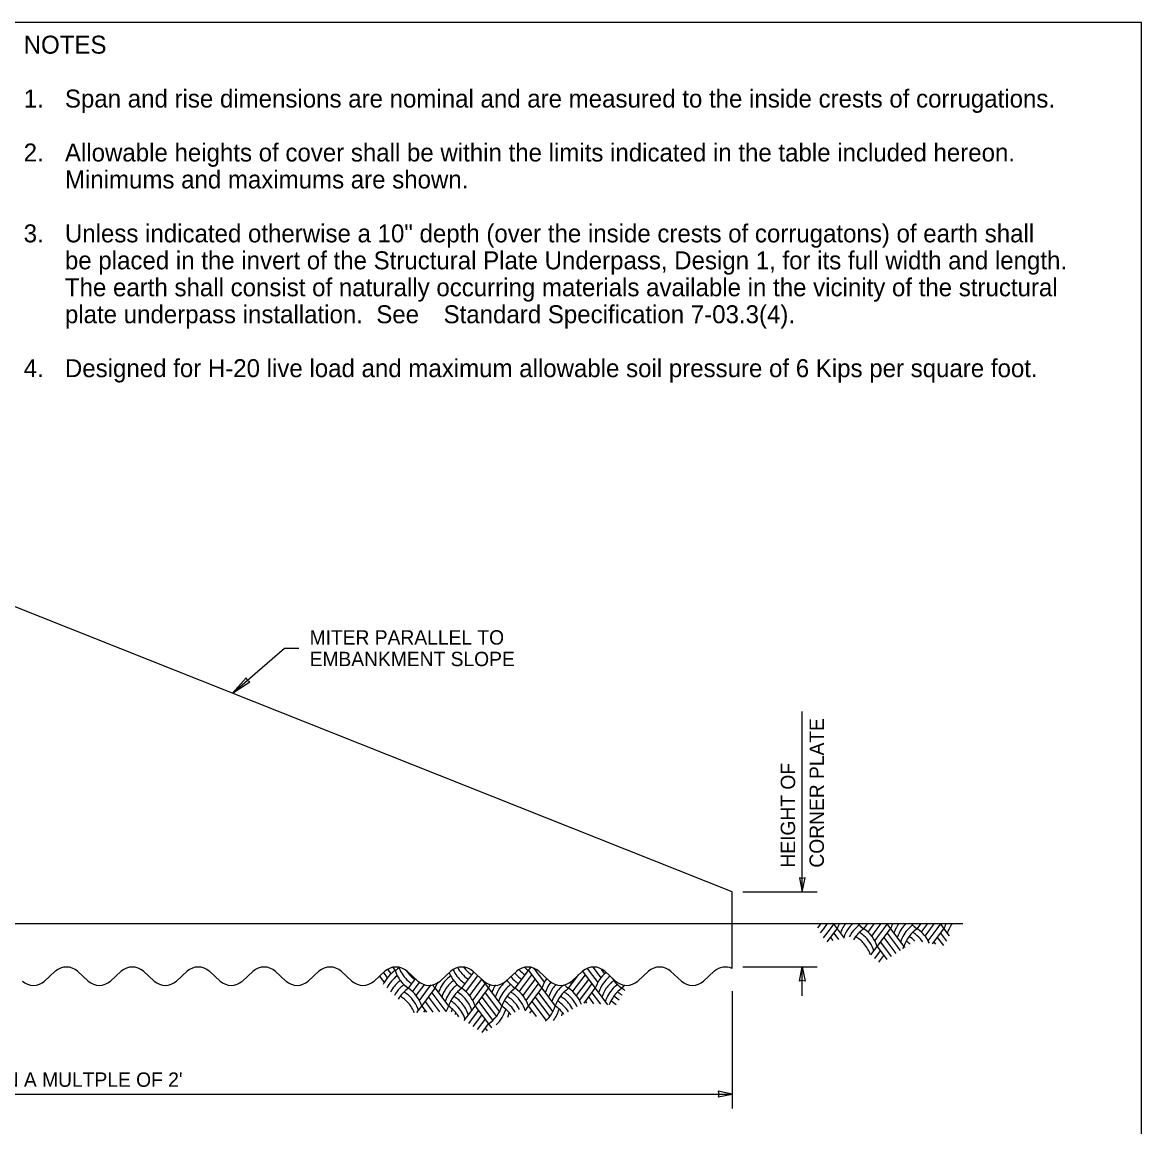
# Model space of a CAD drawing. Extents: x 99862 to 103151, y 100000 to 102076.
# Drawn here: x 101906 to 103151, y 100847 to 102076 of the extents above; entities that cross this region are included whole.
import ezdxf

# ---------------------------------------------------------------- set-up
doc = ezdxf.new("R2010")
doc.units = 0
for name, color, linetype in [('Level 1', 7, 'Continuous'), ('Level 11', 7, 'Continuous'), ('Level 15', 7, 'Continuous'), ('Level 20', 7, 'Continuous'), ('Level 40', 7, 'Continuous'), ('Level 6', 7, 'Continuous'), ('Level 60', 7, 'Continuous'), ('Level 62', 7, 'Continuous')]:
    doc.layers.add(name, color=color, linetype=linetype)

msp = doc.modelspace()

# ---------------------------------------------------------------- linework, layer by layer
at = {"layer": 'Level 1'}
msp.add_lwpolyline([(99862, 99999.5), (103151, 99999.5), (103151, 102075.5), (99862, 102075.5)], close=True, dxfattribs=at)
at = {"layer": 'Level 11'}
for p, q in [((102303, 101014), (102308.3, 101007)), ((102307.4, 101018.1), (102311.7, 101012.3)), ((102312.3, 101021.4), (102315.8, 101016.7)), ((102318, 101023.7), (102320.5, 101020.4)), ((102394.7, 101000.6), (102408.2, 101018.6)), ((102402.1, 101000.6), (102412.6, 101014.5)), ((102454.1, 101000.6), (102469, 101020.4)), ((102461.5, 101000.6), (102472.7, 101015.5)), ((102469, 101020.4), (102471.5, 101023.9)), ((102469, 101020.4), (102483.8, 101000.6)), ((102474.8, 101022.5), (102486.5, 101007)), ((102513.5, 101000.6), (102524.9, 101015.8)), ((102520.9, 101000.6), (102532.1, 101015.5)), ((102529, 101019.6), (102543.2, 101000.6)), ((102534.2, 101022.5), (102545.9, 101007)), ((102540.7, 101023.8), (102549.3, 101012.3)), ((102549.7, 101021.7), (102553.4, 101016.7)), ((102335.3, 101000.6), (102343.1, 101011)), ((102342.7, 101000.6), (102347.8, 101007.4)), ((102350.2, 101000.6), (102353.1, 101004.6)), ((102357.6, 101000.6), (102360.4, 101004.4)), ((102362.2, 101004.3), (102365, 101000.6)), ((102367.5, 101007.1), (102367.7, 101007)), ((102409.6, 101000.6), (102417, 101010.5)), ((102417, 101010.5), (102424.4, 101000.6)), ((102417, 101000.6), (102420.7, 101005.6)), ((102469, 101000.6), (102476.4, 101010.5)), ((102476.4, 101000.6), (102480.1, 101005.6)), ((102528.4, 101000.6), (102535.8, 101010.5)), ((102535.8, 101000.6), (102539.5, 101005.6)), ((102572.9, 101000.6), (102575.9, 101004.6)), ((102340, 100996.9), (102342.7, 101000.6)), ((102344, 100992.5), (102350.2, 101000.6)), ((102347.5, 100987.2), (102357.6, 101000.6)), ((102350.2, 100980.8), (102365, 101000.6)), ((102357.6, 100990.7), (102369.8, 100974.5)), ((102361.3, 100995.7), (102377, 100974.7)), ((102365, 101000.6), (102379.9, 100980.8)), ((102399.4, 100996.9), (102402.1, 101000.6)), ((102403.4, 100992.5), (102409.6, 101000.6)), ((102406.9, 100987.2), (102417, 101000.6)), ((102409.6, 100980.8), (102424.4, 101000.6)), ((102417, 100990.7), (102433.1, 100969.2)), ((102420.7, 100995.7), (102436.6, 100974.5)), ((102424.4, 101000.6), (102439.3, 100980.8)), ((102458.8, 100996.9), (102461.5, 101000.6)), ((102462.8, 100992.5), (102469, 101000.6)), ((102466.3, 100987.2), (102476.4, 101000.6)), ((102469, 100980.8), (102483.8, 101000.6)), ((102476.4, 100990.7), (102492.5, 100969.2)), ((102480.1, 100995.7), (102496, 100974.5)), ((102483.8, 101000.6), (102498.7, 100980.8)), ((102518.2, 100996.9), (102520.9, 101000.6)), ((102522.2, 100992.5), (102528.4, 101000.6)), ((102525.7, 100987.2), (102535.8, 101000.6)), ((102530.9, 100984.2), (102543.2, 101000.6)), ((102535.8, 100990.7), (102541.2, 100983.5)), ((102539.5, 100995.7), (102549, 100983)), ((102543.2, 101000.6), (102556.9, 100982.4)), ((102344.7, 100973.6), (102350.2, 100980.8)), ((102350.2, 100980.8), (102355.3, 100974)), ((102353.9, 100985.8), (102362.5, 100974.2)), ((102397.4, 100964.7), (102409.6, 100980.8)), ((102409.6, 100980.8), (102424.4, 100961)), ((102413.3, 100985.8), (102429.1, 100964.7)), ((102465, 100975.5), (102469, 100980.8)), ((102469, 100980.8), (102477.5, 100969.4)), ((102472.7, 100985.8), (102488.5, 100964.7)), ((102532.1, 100985.8), (102533.4, 100984)), ((102352.3, 100973.9), (102353.9, 100975.9)), ((102402.4, 100961.4), (102413.3, 100975.9)), ((102407.3, 100958.1), (102417, 100970.9)), ((102412.3, 100954.8), (102420.7, 100966)), ((102470.4, 100972.9), (102472.7, 100975.9)), ((102475.8, 100970.2), (102476.4, 100970.9)), ((102417.2, 100951.5), (102424.4, 100961)), ((102420.7, 100956.1), (102422.9, 100953.2)), ((102424.4, 100961), (102427.8, 100956.5))]:
    msp.add_line(p, q, dxfattribs=at)
for centre, start, end in [((102341.4, 100989.2), 123.9036, 155.3622), ((102345.1, 100984.3), 126.3063, 153.8683), ((102299.5, 101051.6), 303.9036, 312.3733), ((102356.3, 101031.8), 197.6434, 236.0964), ((102360, 101036.8), 200.2432, 228.9599), ((102363.7, 101041.7), 215.4772, 220.9416), ((102363.7, 101041.7), 220.9415, 236.0964), ((102404.5, 100984.3), 126.3063, 154.2266), ((102415.7, 101031.8), 201.4874, 236.0964), ((102419.4, 101036.8), 204.5498, 228.9599), ((102423.1, 101041.7), 208.7333, 220.9416), ((102423.1, 101041.7), 220.9415, 236.0964), ((102426.8, 101046.7), 217.4338, 236.0964), ((102482.5, 101041.7), 219.7756, 220.9416), ((102482.5, 101041.7), 220.9415, 236.0964), ((102486.2, 101046.7), 222.6882, 236.0964), ((102489.9, 101051.6), 228.0122, 236.0964), ((102545.6, 101046.7), 235.9753, 236.0964), ((102579, 100989.2), 129.4402, 162.3566), ((102582.7, 100984.3), 127.6651, 154.2266), ((102348.8, 100979.3), 127.1006, 145.4911), ((102352.6, 100974.4), 126.331, 135.7128), ((102360, 101036.8), 228.9599, 236.0964), ((102400.8, 100989.2), 151.2509, 162.3566), ((102408.2, 100979.3), 127.1006, 145.4911), ((102412, 100974.4), 126.331, 135.7128), ((102419.4, 101036.8), 228.9599, 236.0964), ((102460.2, 100989.2), 155.6268, 162.3566), ((102463.9, 100984.3), 147.6019, 154.2266), ((102467.6, 100979.3), 127.1006, 145.4911), ((102471.4, 100974.4), 126.331, 135.7128), ((102475.1, 101031.8), 216.2594, 236.0964), ((102478.8, 101036.8), 218.0196, 228.9599), ((102478.8, 101036.8), 228.9599, 236.0964), ((102519.6, 100989.2), 143.8002, 162.3566), ((102523.3, 100984.3), 141.3871, 154.2266), ((102527, 100979.3), 137.4919, 145.4911), ((102530.7, 100974.4), 127.1068, 135.7128), ((102534.5, 101031.8), 226.9894, 236.0964), ((102538.2, 101036.8), 231.3576, 236.0964), ((102541.9, 101041.7), 234.179, 236.0964), ((102586.4, 100979.3), 127.1006, 145.4911), ((102593.9, 101031.8), 211.6153, 236.0964), ((102590.1, 100974.4), 126.331, 135.7128), ((102348.8, 100979.3), 145.491, 152.386), ((102352.6, 100974.4), 135.7127, 150.9165), ((102356.3, 100969.4), 123.9036, 149.4574), ((102306.9, 100959.5), 40.9413, 59.3021), ((102310.6, 100964.5), 48.9597, 58.5465), ((102314.3, 100969.4), 17.6434, 56.0963), ((102310.6, 100964.5), 17.6434, 48.9597), ((102404.5, 100984.3), 154.2265, 162.3566), ((102408.2, 100979.3), 145.491, 162.3566), ((102412, 100974.4), 135.7127, 162.3566), ((102415.7, 100969.4), 123.9036, 162.3566), ((102366.3, 100959.5), 40.9413, 59.3021), ((102370, 100964.5), 48.9597, 58.5465), ((102373.7, 100969.4), 17.6434, 56.0963), ((102370, 100964.5), 17.6434, 48.9597), ((102463.9, 100984.3), 154.2265, 162.3566), ((102467.6, 100979.3), 145.491, 162.3566), ((102471.4, 100974.4), 135.7127, 162.3566), ((102475.1, 100969.4), 123.9036, 162.3566), ((102425.7, 100959.5), 40.9413, 59.3021), ((102429.4, 100964.5), 48.9597, 58.5465), ((102433.1, 100969.4), 17.6434, 56.0963), ((102429.4, 100964.5), 17.6434, 48.9597), ((102523.3, 100984.3), 154.2265, 162.3566), ((102527, 100979.3), 145.491, 162.3566), ((102530.7, 100974.4), 135.7127, 162.3566), ((102534.5, 100969.4), 123.9036, 162.3566), ((102485.1, 100959.5), 40.9413, 59.3021), ((102488.8, 100964.5), 48.9597, 58.5465), ((102492.5, 100969.4), 20.8162, 56.0963), ((102488.8, 100964.5), 24.512, 48.9597), ((102582.7, 100984.3), 154.2265, 162.3566), ((102586.4, 100979.3), 145.491, 162.3566), ((102590.1, 100974.4), 135.7127, 162.3566), ((102593.9, 100969.4), 123.9036, 159.9687), ((102544.5, 100959.5), 48.0052, 59.3021), ((102548.2, 100964.5), 48.9597, 58.5465), ((102551.9, 100969.4), 49.9036, 56.0963), ((102548.2, 100964.5), 48.9564, 48.9597), ((102306.9, 100959.5), 21.7659, 40.9414), ((102344, 100992.2), 332.2846, 342.3566), ((102358.9, 100949.6), 30.7324, 56.0964), ((102362.6, 100954.6), 31.3316, 58.4874), ((102347.8, 100987.3), 339.7971, 345.0113), ((102366.3, 100959.5), 17.6434, 40.9414), ((102403.4, 100992.2), 303.9036, 342.3566), ((102407.2, 100987.3), 313.1894, 345.0113), ((102418.3, 100949.6), 34.3365, 56.0964), ((102422, 100954.6), 31.3316, 58.4874), ((102425.7, 100959.5), 28.0487, 40.9414), ((102462.8, 100992.2), 311.939, 342.3566), ((102466.6, 100987.3), 322.9192, 345.0113), ((102477.7, 100949.6), 35.5161, 56.0964), ((102481.4, 100954.6), 31.8464, 58.4874), ((102485.1, 100959.5), 28.1839, 40.9414), ((102540.8, 100954.6), 47.0522, 58.4874), ((102351.5, 100982.3), 343.0498, 346.3199), ((102362.6, 100954.6), 17.6434, 31.3317), ((102410.9, 100982.3), 338.4157, 346.3199), ((102422, 100954.6), 31.1968, 31.3317), ((102470.3, 100982.3), 340.8723, 346.3199)]:
    msp.add_arc(centre, 37.6, start, end, dxfattribs=at)
at = {"layer": 'Level 15'}
for p, q in [((102139.7, 101328.9), (102197.3, 101379.1)), ((102197.3, 101379.1), (102213.3, 101379.1)), ((102773.5, 101107.8), (102773.5, 101308.5)), ((102707.5, 101107.8), (102789.9, 101107.8)), ((102707.5, 101024.4), (102789.9, 101024.4)), ((102773.5, 100992.4), (102773.5, 101024.4)), ((102695.5, 100997.6), (102695.5, 100867)), ((101185, 100883), (102695.5, 100883))]:
    msp.add_line(p, q, dxfattribs=at)
for points in [[(102139.7, 101328.9), (102158.8, 101341.7), (102156.1, 101343.3), (102154.9, 101346.2)], [(102773.5, 101107.8), (102776.6, 101123.5), (102773.5, 101122.8), (102770.4, 101123.5)], [(102773.5, 101024.4), (102776.6, 101008.6), (102773.5, 101009.4), (102770.4, 101008.6)], [(102695.5, 100883), (102679.7, 100886.1), (102680.5, 100883), (102679.7, 100879.9)]]:
    msp.add_lwpolyline(points, close=True, dxfattribs=at)
at = {"layer": 'Level 40'}
for p, q in [((101174.7, 101072.7), (102695.5, 101072.7)), ((102695.5, 101072.7), (102952.2, 101072.7)), ((101942.4, 101019.6), (101930.5, 101008.7)), ((101967.2, 101019.6), (101979.1, 101008.7)), ((102015.7, 101019.6), (102003.8, 101008.7)), ((102040.5, 101019.6), (102052.4, 101008.7)), ((102089.1, 101019.6), (102077.1, 101008.7)), ((102113.8, 101019.6), (102125.7, 101008.7)), ((102162.4, 101019.6), (102150.5, 101008.7)), ((102187.1, 101019.6), (102199, 101008.7)), ((102235.7, 101019.6), (102223.8, 101008.7)), ((102260.4, 101019.6), (102272.4, 101008.7)), ((102309, 101019.6), (102297.1, 101008.7)), ((102333.8, 101019.6), (102345.7, 101008.7)), ((102382.3, 101019.6), (102370.4, 101008.7)), ((102407.1, 101019.6), (102419, 101008.7)), ((102455.7, 101019.6), (102443.7, 101008.7)), ((102480.4, 101019.6), (102492.3, 101008.7)), ((102529, 101019.6), (102517.1, 101008.7)), ((102553.7, 101019.6), (102565.6, 101008.7)), ((102602.3, 101019.6), (102590.4, 101008.7)), ((102627, 101019.6), (102639, 101008.7)), ((102675.6, 101019.6), (102663.7, 101008.7))]:
    msp.add_line(p, q, dxfattribs=at)
for centre, start, end in [((101954.8, 101006), 47.5765, 132.4235), ((102028.1, 101006), 47.5765, 132.4235), ((102101.4, 101006), 47.5765, 132.4235), ((102174.7, 101006), 47.5765, 132.4235), ((102248.1, 101006), 47.5765, 132.4235), ((102321.4, 101006), 47.5765, 132.4235), ((102394.7, 101006), 47.5765, 132.4235), ((102468, 101006), 47.5765, 132.4235), ((102541.4, 101006), 47.5765, 132.4235), ((102614.7, 101006), 47.5765, 132.4235), ((102688, 101006), 65.9698, 132.4235), ((101918.1, 101022.2), 227.5762, 312.4235), ((101991.4, 101022.2), 227.5762, 312.4235), ((102064.8, 101022.2), 227.5762, 312.4235), ((102138.1, 101022.2), 227.5762, 312.4235), ((102211.4, 101022.2), 227.5762, 312.4235), ((102284.7, 101022.2), 227.5762, 312.4235), ((102358.1, 101022.2), 227.5762, 312.4235), ((102431.4, 101022.2), 227.5762, 312.4235), ((102504.7, 101022.2), 227.5762, 312.4235), ((102578, 101022.2), 227.5762, 312.4235), ((102651.3, 101022.2), 227.5762, 312.4235)]:
    msp.add_arc(centre, 18.3, start, end, dxfattribs=at)
at = {"layer": 'Level 6'}
for p, q in [((102695.5, 101107.8), (101897.9, 101425.1)), ((102695.5, 101022.8), (102695.5, 101107.8))]:
    msp.add_line(p, q, dxfattribs=at)
at = {"layer": 'Level 60'}
msp.add_line((103151, 102075.5), (103151, 102075.5), dxfattribs=at)
at = {"layer": 'Level 62'}
for p, q in [((102790.6, 101067.8), (102794.3, 101072.7)), ((102793.9, 101062.3), (102797.4, 101066.9)), ((102797.2, 101056.8), (102804.8, 101066.9)), ((102797.4, 101066.9), (102801.7, 101072.7)), ((102801.3, 101052.4), (102812.3, 101066.9)), ((102804.8, 101066.9), (102808.5, 101071.9)), ((102807.9, 101072.7), (102812.3, 101066.9)), ((102812.3, 101066.9), (102820.1, 101056.5)), ((102842, 101066.9), (102846.3, 101072.7)), ((102846.6, 101063.2), (102849.4, 101066.9)), ((102849.4, 101066.9), (102853.7, 101072.7)), ((102850.7, 101058.8), (102856.8, 101066.9)), ((102854.1, 101053.5), (102864.2, 101066.9)), ((102856.8, 101066.9), (102861.1, 101072.7)), ((102856.8, 101047.1), (102871.7, 101066.9)), ((102864.2, 101066.9), (102867.9, 101071.9)), ((102867.3, 101072.7), (102871.7, 101066.9)), ((102871.7, 101066.9), (102886.5, 101047.1)), ((102901.3, 101066.9), (102905.7, 101072.7)), ((102906, 101063.2), (102908.8, 101066.9)), ((102908.8, 101066.9), (102913.1, 101072.7)), ((102910.1, 101058.8), (102916.2, 101066.9)), ((102913.5, 101053.5), (102923.6, 101066.9)), ((102916.2, 101066.9), (102920.5, 101072.7)), ((102918.5, 101050.2), (102931, 101066.9)), ((102923.6, 101066.9), (102927.3, 101071.9)), ((102926.7, 101072.7), (102931, 101066.9)), ((102931, 101066.9), (102936.9, 101059.1)), ((102804.8, 101057), (102807.3, 101053.7)), ((102808.5, 101062), (102813.7, 101055.1)), ((102860.5, 101052.1), (102872.5, 101036.1)), ((102864.2, 101057), (102877.5, 101039.4)), ((102867.9, 101062), (102882.4, 101042.6)), ((102919.9, 101052.1), (102921.8, 101049.6)), ((102923.6, 101057), (102930.4, 101048.1)), ((102927.3, 101062), (102934.1, 101053)), ((102849.7, 101037.7), (102856.8, 101047.1)), ((102854.2, 101033.7), (102860.5, 101042.2)), ((102856.8, 101047.1), (102867.5, 101032.8)), ((102858.7, 101029.8), (102864.2, 101037.2))]:
    msp.add_line(p, q, dxfattribs=at)
for centre, start, end in [((102848.1, 101055.5), 152.8374, 162.3566), ((102851.8, 101050.6), 154.2265, 162.3566), ((102851.8, 101050.6), 143.9679, 154.2266), ((102855.5, 101045.6), 145.491, 162.3566), ((102855.5, 101045.6), 133.9489, 145.4911), ((102859.2, 101040.7), 135.7127, 153.0426), ((102862.9, 101035.7), 123.9036, 149.9545), ((102859.2, 101040.7), 126.331, 135.7128), ((102862.9, 101098.1), 222.5748, 236.0964), ((102821, 101035.7), 17.6434, 56.0963), ((102866.6, 101103.1), 233.9276, 236.0964), ((102907.5, 101055.5), 152.8374, 162.3566), ((102911.2, 101050.6), 154.2265, 162.3566), ((102911.2, 101050.6), 143.9679, 154.2266), ((102914.9, 101045.6), 145.491, 162.3566), ((102918.6, 101040.7), 135.7127, 162.3566), ((102914.9, 101045.6), 133.9489, 145.4911), ((102922.3, 101035.7), 123.9036, 162.3566), ((102918.6, 101040.7), 126.331, 135.7128), ((102922.3, 101098.1), 222.5748, 236.0964), ((102880.4, 101035.7), 23.7265, 56.0963), ((102926, 101103.1), 233.9276, 236.0964), ((102966.9, 101055.5), 152.8374, 162.3566), ((102970.6, 101050.6), 154.2265, 162.3566), ((102970.6, 101050.6), 143.9679, 154.2266), ((102813.6, 101025.8), 40.9413, 59.3021), ((102817.3, 101030.8), 48.9597, 58.5465), ((102817.3, 101030.8), 17.6434, 48.9597), ((102869.3, 101020.9), 50.2159, 58.4874), ((102873, 101025.8), 46.9028, 59.3021), ((102876.7, 101030.8), 48.9597, 58.5465), ((102876.7, 101030.8), 34.6569, 48.9597), ((102813.6, 101025.8), 19.249, 40.9414), ((102850.7, 101058.5), 338.4875, 342.3566), ((102865.5, 101015.9), 53.5882, 56.0964)]:
    msp.add_arc(centre, 37.6, start, end, dxfattribs=at)

# ---------------------------------------------------------------- texts
at = {"layer": 'Level 20'}
for s, height, p in [('NOTES', 20, (101907.2, 102040.7)), ('1.', 20, (101907.2, 101980.7)), ('Span and rise dimensions are nominal and are measured to the inside crests of corrugations.', 20, (101953.1, 101980.7)), ('2.', 20, (101907.2, 101920.7)), ('Allowable heights of cover shall be within the limits indicated in the table included hereon.', 20, (101953.1, 101920.7)), ('Minimums and maximums are shown.', 20, (101953.1, 101890.7)), ('3.', 20, (101907.2, 101830.7)), ('Unless indicated otherwise a 10" depth (over the inside crests of corrugatons) of earth shall', 20, (101953.1, 101830.7)), ('be placed in the invert of the Structural Plate Underpass, Design 1, for its full width and length.', 20, (101953.1, 101800.7)), ('The earth shall consist of naturally occurring materials available in the vicinity of the structural', 20, (101953.1, 101770.7)), ('plate underpass installation.  See ', 20, (101953.1, 101740.7)), ('Standard Specification 7-03.3(4).', 20, (102374.4, 101740.7)), ('4.', 20, (101907.2, 101680.7)), ('Designed for H-20 live load and maximum allowable soil pressure of 6 Kips per square foot.', 20, (101953.1, 101680.7)), ('MITER PARALLEL TO', 16, (102225.3, 101383.1)), ('EMBANKMENT SLOPE', 16, (102225.3, 101359.1)), ("LENGTH IN A MULTPLE OF 2'", 16, (101787.4, 100891))]:
    msp.add_text(s, height=height, dxfattribs=at).set_placement(p)
for s, p in [('CORNER PLATE', (102797.5, 101134.9)), ('HEIGHT OF', (102765.5, 101134.9))]:
    msp.add_text(s, height=16, rotation=90, dxfattribs=at).set_placement(p)

doc.saveas('drawing.dxf')
